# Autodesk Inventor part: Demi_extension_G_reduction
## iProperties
Shininess: 64.0
Length Units: 11269
Angle Units: 11279
Time Units: 11290
Mass Units: 11283
Length Display Precision: 3
Angle Display Precision: 2
Compacted: True
Part Number: Demi_extension_G_reduction
Document SubType Name: Modeling
Created: 2008-02
Material: Acier inoxydable, austénitique
Designer: Pascal
Density: 8.03 g/cm^3
Density: 0.0
Volumn: 0.0
Area: 0.0
PropertySet Name: Model Information
Control State: 0
Master: False
Checked Out: False
MATIERE_PIECE: X2CrNi 18-11
OBSERVATIONS: Tôle ep. 15/10
DESIGNATION: Demi-extension gauche
Author: Pascal
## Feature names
1. Extrusion1
2. Extrusion2
3. Extrusion3
